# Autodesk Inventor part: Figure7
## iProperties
Shininess: 77.0
Length Units: 11269
Angle Units: 11279
Time Units: 11290
Mass Units: 11283
Length Display Precision: 3
Angle Display Precision: 2
Created: 2002-01
Part Number: Figure7
Document SubType Name: Modeling
Designer: CADSoft
Density: 0.0
Volumn: 0.0
Area: 0.0
PropertySet Name: Model Information
Control State: 0
Master: False
Checked Out: False
Author: CADSoft
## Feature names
1. Coil3
